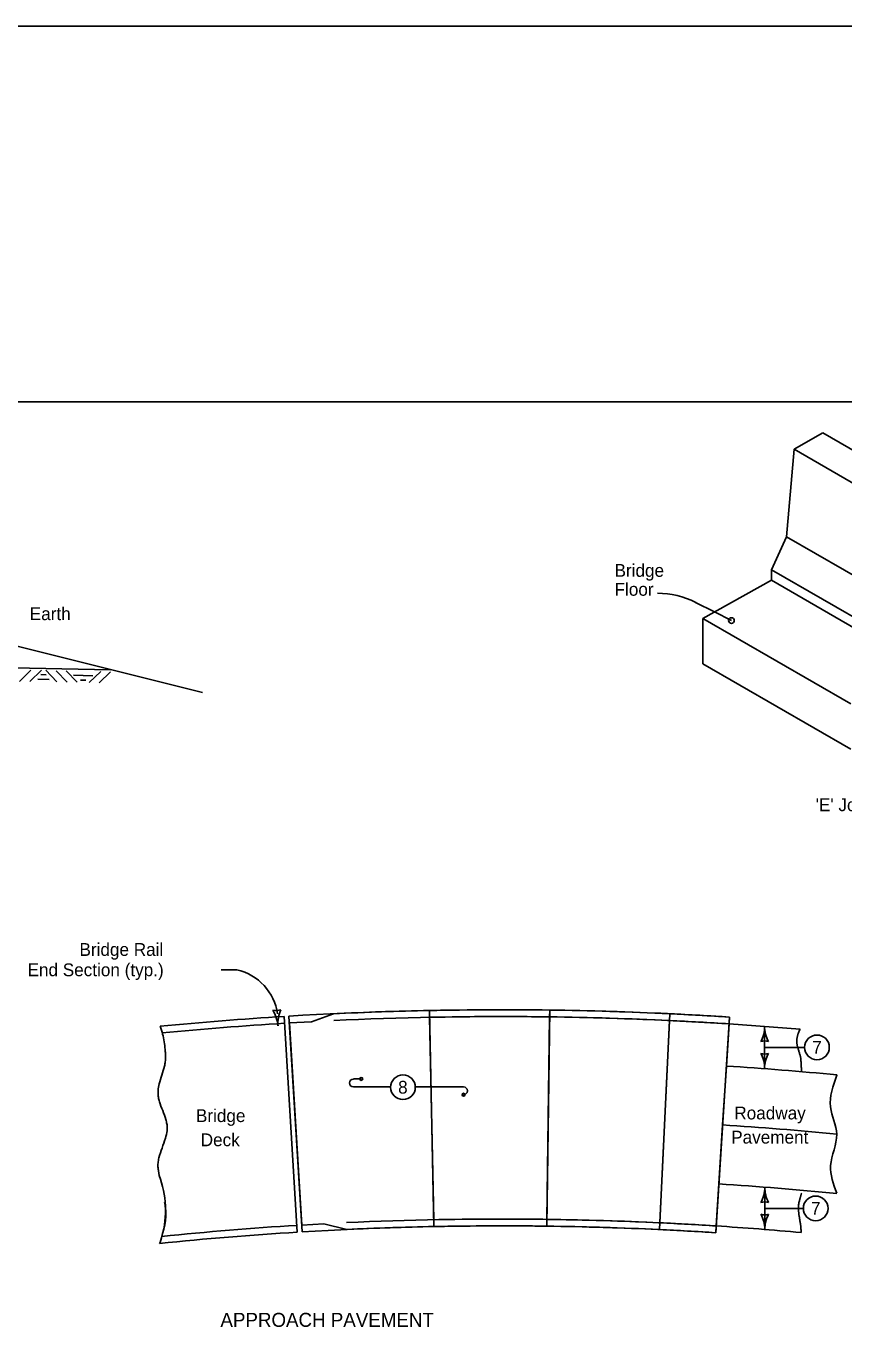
# Model space of a CAD drawing. Extents: x -2135039 to -2124495, y -2139046 to -2132546.
# Drawn here: x -2126601 to -2125580, y -2134174 to -2132546 of the extents above; entities that cross this region are included whole.
import ezdxf

# ---------------------------------------------------------------- set-up
doc = ezdxf.new("R2010")
doc.units = 0
for name, color, linetype in [('BridgeSuperStructureExisting', 7, 'Continuous'), ('Default', 7, 'Continuous'), ('dsnAlignmentStation', 7, 'Continuous'), ('dsnCellElements', 7, 'Continuous'), ('dsnStdLabel', 7, 'Continuous'), ('dsnStdLineWork', 7, 'Continuous'), ('TC_Barrier', 7, 'Continuous')]:
    doc.layers.add(name, color=color, linetype=linetype)

msp = doc.modelspace()

# ---------------------------------------------------------------- linework, layer by layer
at = {"layer": 'BridgeSuperStructureExisting'}
for p, q in [((-2125466.3, -2133291.3), (-2125651.3, -2133184.5)), ((-2125485.2, -2133332.6), (-2125670.2, -2133225.8)), ((-2125670.2, -2133225.8), (-2125670.2, -2133238.9)), ((-2125764.8, -2133266.6), (-2125741.4, -2133278.4)), ((-2125741.4, -2133278.4), (-2125720.1, -2133289.2)), ((-2126628.9, -2133317.2), (-2126380.7, -2133379.3)), ((-2126673.1, -2133347.1), (-2126495.3, -2133350.6)), ((-2126594.9, -2133351.3), (-2126609.3, -2133365.2)), ((-2126581.9, -2133351.3), (-2126596.3, -2133365.2)), ((-2126576.5, -2133351.4), (-2126562.6, -2133365.9)), ((-2126563.5, -2133351.9), (-2126549.6, -2133366.4)), ((-2126551, -2133352), (-2126537.2, -2133366.4)), ((-2126507.8, -2133352.8), (-2126522.2, -2133366.7)), ((-2126495.4, -2133353.3), (-2126509.8, -2133367.2)), ((-2126337.7, -2133725.6), (-2126357.2, -2133725.6)), ((-2126272.2, -2133792), (-2126244.6, -2133790.7)), ((-2126244.6, -2133790.7), (-2126272.2, -2133792)), ((-2126272.2, -2133792), (-2126256.6, -2134044.5)), ((-2126244.6, -2133790.7), (-2126217, -2133780.5)), ((-2126217, -2133780.5), (-2126244.6, -2133790.7)), ((-2126091.8, -2134046.4), (-2126097.3, -2133776.4)), ((-2126097.3, -2133776.4), (-2126097.1, -2133784.9)), ((-2126097.1, -2133784.9), (-2126097.3, -2133776.4)), ((-2126097.1, -2133784.9), (-2126091.9, -2134037.9)), ((-2126091.9, -2134037.9), (-2126097.1, -2133784.9)), ((-2125950.8, -2134045.9), (-2125947.1, -2133775.9)), ((-2125947.2, -2133784.4), (-2125950.7, -2134037.4)), ((-2125950.7, -2134037.4), (-2125947.2, -2133784.4)), ((-2125947.1, -2133775.9), (-2125947.2, -2133784.4)), ((-2125947.2, -2133784.4), (-2125947.1, -2133775.9)), ((-2125810, -2134050.2), (-2125797.2, -2133780.5)), ((-2125809.6, -2134041.7), (-2125797.6, -2133789)), ((-2125797.6, -2133789), (-2125809.6, -2134041.7)), ((-2125797.2, -2133780.5), (-2125797.6, -2133789)), ((-2125797.6, -2133789), (-2125797.2, -2133780.5)), ((-2125723, -2133793.1), (-2125722.4, -2133784.7)), ((-2125678.7, -2133849), (-2125678.7, -2133796.2)), ((-2125678.7, -2133822.5), (-2125649.2, -2133822.5)), ((-2125649.2, -2133822.5), (-2125628.6, -2133822.5)), ((-2126182.4, -2133862), (-2126192.2, -2133862)), ((-2126145.7, -2133871.9), (-2126192.2, -2133871.9)), ((-2126115, -2133871.9), (-2126054.7, -2133871.9)), ((-2126435, -2133982.6), (-2126436.1, -2133973.7)), ((-2125678.5, -2134050), (-2125678.5, -2133997.4)), ((-2125678.5, -2134023.7), (-2125649, -2134023.7)), ((-2125649, -2134023.7), (-2125630.2, -2134023.7)), ((-2126256.6, -2134044.5), (-2126229.1, -2134042.8)), ((-2126256.6, -2134044.5), (-2126229.1, -2134042.8)), ((-2126229.1, -2134042.8), (-2126200.5, -2134050)), ((-2126229.1, -2134042.8), (-2126200.5, -2134050)), ((-2126091.9, -2134037.9), (-2126091.8, -2134046.4)), ((-2126091.8, -2134046.4), (-2126091.9, -2134037.9)), ((-2125950.7, -2134037.4), (-2125950.8, -2134045.9)), ((-2125950.8, -2134045.9), (-2125950.7, -2134037.4)), ((-2125809.6, -2134041.7), (-2125810, -2134050.2)), ((-2125810, -2134050.2), (-2125809.6, -2134041.7)), ((-2125739.8, -2134054.1), (-2125739.2, -2134045.6))]:
    msp.add_line(p, q, dxfattribs=at)
for points in [[(-2125606, -2133054.7), (-2125240, -2133266), (-2125149.5, -2133318.2), (-2125104.3, -2133344.4), (-2125132.5, -2133360.7), (-2125185.3, -2133338.9), (-2125275.9, -2133286.7), (-2125456.9, -2133182.1), (-2125641.9, -2133075.3)], [(-2125641.9, -2133075.3), (-2125606, -2133054.7)], [(-2125670.2, -2133225.8), (-2125651.3, -2133184.5), (-2125641.9, -2133075.3)], [(-2125670.2, -2133238.9), (-2125756, -2133286.5)], [(-2125485.2, -2133345.7), (-2125670.2, -2133238.9)], [(-2125756, -2133286.5), (-2125571, -2133393.3)], [(-2125756, -2133343.1), (-2125756, -2133286.5)], [(-2125571, -2133449.9), (-2125756, -2133343.1)], [(-2126586.5, -2133362.6), (-2126572.3, -2133362.9)], [(-2126582.6, -2133356.8), (-2126576, -2133357)], [(-2126541.6, -2133357.6), (-2126517.5, -2133358.1)], [(-2126532.9, -2133363.6), (-2126526.4, -2133363.7)], [(-2125739.2, -2134045.6), (-2125735.8, -2133993), (-2125731.1, -2133919.4), (-2125726.4, -2133845.8), (-2125723, -2133793.1)]]:
    msp.add_lwpolyline(points, dxfattribs=at)
for centre in [(-2125613.3, -2133822.5), (-2126130.3, -2133872.3), (-2126130.3, -2133872.3), (-2125614.9, -2134023.7)]:
    msp.add_circle(centre, 15.4, dxfattribs=at)
for centre, radius, start, end in [((-2125812.5, -2133361.1), 105.9, 63.2177, 90), ((-2126352.8, -2133790.5), 66.7, 8.4828, 76.8823), ((-2126007.1, -2138203.4), 4427.9, 89.2234, 91.1665), ((-2126007.1, -2138203.4), 4427.9, 91.1665, 92.7162), ((-2126007.1, -2138203.4), 4419.4, 86.3134, 92.7162), ((-2126007.1, -2138203.4), 4419.4, 89.2234, 91.1665), ((-2126007.1, -2138203.4), 4419.4, 89.2234, 91.1665), ((-2126007.1, -2138203.4), 4419.4, 87.2821, 89.2234), ((-2126007.1, -2138203.4), 4419.4, 87.2821, 89.2234), ((-2126007.1, -2138203.4), 4427.9, 87.2821, 89.2234), ((-2126007.1, -2138203.4), 4419.4, 86.3134, 87.2821), ((-2126007.1, -2138203.4), 4419.4, 86.3134, 87.2821), ((-2126007.1, -2138203.4), 4427.9, 86.3134, 87.2821), ((-2126007.1, -2138203.4), 4419.4, 85.1616, 86.3134), ((-2125718.8, -2133796.2), 40.2, 331.9275, 360), ((-2125638.5, -2133796.2), 40.2, 180, 208.0725), ((-2125605, -2133816), 33.6, 151.08, 159.8686), ((-2125678.7, -2133829.9), 15.5, 72.2666, 107.7334), ((-2125678.7, -2133815.3), 15.5, 252.2666, 287.7333), ((-2125718.8, -2133849), 40.2, 360, 28.0725), ((-2125638.5, -2133849), 40.2, 151.9275, 180), ((-2126007.1, -2138203.4), 4366.6, 84.4974, 86.3134), ((-2125507.8, -2133892.3), 88, 156.2644, 156.5217), ((-2126192.2, -2133867), 4.92, 90, 270), ((-2126054.7, -2133876.8), 4.92, 270, 90), ((-2126545.3, -2134025.8), 118.5, 343.9162, 21.4054), ((-2126007.1, -2138203.4), 4219.1, 84.307, 86.3134), ((-2125718.7, -2133997.4), 40.2, 331.9275, 360), ((-2125638.3, -2133997.4), 40.2, 180, 208.0725), ((-2125678.5, -2134031.1), 15.5, 72.2666, 107.7334), ((-2125678.5, -2134016.3), 15.5, 252.2666, 287.7333), ((-2125718.7, -2134050), 40.2, 360, 28.0725), ((-2125638.3, -2134050), 40.2, 151.9275, 180), ((-2126007.1, -2138203.4), 4166.4, 86.3134, 92.666), ((-2126007.1, -2138203.4), 4157.9, 91.1665, 92.666), ((-2126007.1, -2138203.4), 4166.4, 89.2234, 91.1665), ((-2126007.1, -2138203.4), 4166.4, 89.2234, 91.1665), ((-2126007.1, -2138203.4), 4157.9, 89.2234, 91.1665), ((-2126007.1, -2138203.4), 4157.9, 87.2821, 89.2234), ((-2126007.1, -2138203.4), 4166.4, 87.2821, 89.2234), ((-2126007.1, -2138203.4), 4166.4, 87.2821, 89.2234), ((-2126007.1, -2138203.4), 4157.9, 86.3134, 87.2821), ((-2126007.1, -2138203.4), 4166.4, 86.3134, 87.2821), ((-2126007.1, -2138203.4), 4166.4, 86.3134, 87.2821), ((-2126007.1, -2138203.4), 4166.4, 84.8485, 86.3134)]:
    msp.add_arc(centre, radius, start, end, dxfattribs=at)
for points in [[(-2126433.6, -2133796.1), (-2126430.5, -2133805.8), (-2126428.5, -2133815.5), (-2126427.3, -2133825.2), (-2126427, -2133830.1), (-2126426.9, -2133834.9), (-2126427.2, -2133840.5), (-2126428.2, -2133846), (-2126431.4, -2133857.1), (-2126434.7, -2133868.2), (-2126436.1, -2133876.5), (-2126436.1, -2133877.9), (-2126436.2, -2133879.3), (-2126435.7, -2133884.9), (-2126434.4, -2133890.4), (-2126430.4, -2133901.5), (-2126426.5, -2133912.6), (-2126425.2, -2133918.1), (-2126424.8, -2133923.6), (-2126424.9, -2133925.2), (-2126425, -2133926.7), (-2126427, -2133936), (-2126431.2, -2133948.3), (-2126435.1, -2133960.7), (-2126436.2, -2133966.9), (-2126436.2, -2133973.2), (-2126435.9, -2133975.6)], [(-2125588.6, -2133857.2), (-2125596.3, -2133896.9), (-2125588.6, -2133931), (-2125596.3, -2133970.2), (-2125588.6, -2134004.7)], [(-2126428.1, -2134016.5), (-2126426.9, -2134022.7), (-2126433.7, -2134066.1)]]:
    msp.add_spline(points, degree=3, dxfattribs=at)
for points in [[(-2125636.5, -2133804.4), (-2125636.7, -2133804.9), (-2125636.9, -2133805.4), (-2125637, -2133805.9), (-2125637.2, -2133806.4), (-2125637.3, -2133806.9), (-2125637.4, -2133807.4), (-2125637.7, -2133808.4), (-2125637.9, -2133809.4), (-2125638.1, -2133810.4), (-2125638.3, -2133811.4), (-2125638.4, -2133812.4), (-2125638.4, -2133813.4), (-2125638.5, -2133813.9), (-2125638.5, -2133814.4), (-2125638.5, -2133814.9), (-2125638.5, -2133815.4), (-2125638.5, -2133815.9), (-2125638.4, -2133816.4), (-2125638.4, -2133817.3), (-2125638.3, -2133818.2), (-2125638.1, -2133819.2), (-2125638, -2133820.1), (-2125637.8, -2133821.1), (-2125637.5, -2133822), (-2125637, -2133823.9), (-2125636.4, -2133825.8), (-2125635.8, -2133827.6), (-2125635.3, -2133829.5), (-2125634.7, -2133831.4), (-2125634.2, -2133833.3), (-2125633.9, -2133834.2), (-2125633.7, -2133835.2), (-2125633.6, -2133836.2), (-2125633.4, -2133837.1), (-2125633.3, -2133838.1), (-2125633.3, -2133839.1), (-2125633.2, -2133840.6), (-2125633.1, -2133842.1), (-2125633, -2133843.6), (-2125633, -2133845.1), (-2125632.9, -2133846.6), (-2125632.8, -2133848.1), (-2125632.7, -2133849.6), (-2125632.7, -2133851.1), (-2125632.6, -2133852.6), (-2125632.6, -2133852.7), (-2125632.6, -2133852.8), (-2125632.6, -2133852.8)], [(-2125632.4, -2134004.7), (-2125632.8, -2134005.5), (-2125633.1, -2134006.4), (-2125633.3, -2134007.3), (-2125633.6, -2134008.2), (-2125633.9, -2134009.1), (-2125634.2, -2134009.9), (-2125634.7, -2134011.7), (-2125635.1, -2134013.4), (-2125635.5, -2134015.2), (-2125636, -2134017.8), (-2125636.4, -2134020.5), (-2125636.4, -2134023.2), (-2125636.4, -2134023.6), (-2125636.4, -2134024.1), (-2125636.4, -2134024.5), (-2125636.4, -2134024.9), (-2125636.4, -2134025.4), (-2125636.4, -2134025.8), (-2125636.3, -2134026.8), (-2125636.2, -2134027.8), (-2125636.1, -2134028.8), (-2125636, -2134029.8), (-2125635.9, -2134030.8), (-2125635.8, -2134031.8), (-2125635.4, -2134033.7), (-2125635.1, -2134035.7), (-2125634.8, -2134037.7), (-2125634.5, -2134039.7), (-2125634.2, -2134041.6), (-2125633.9, -2134043.6), (-2125633.7, -2134044.6), (-2125633.6, -2134045.6), (-2125633.5, -2134046.6), (-2125633.4, -2134047.6), (-2125633.3, -2134048.6), (-2125633.3, -2134049.6), (-2125633.2, -2134051), (-2125633.1, -2134052.4), (-2125633, -2134053.8)]]:
    msp.add_open_spline(points, degree=3, dxfattribs=at)
at = {"layer": 'Default'}
for p, q in [((-2126262.3, -2134053.3), (-2126278.8, -2133783.8)), ((-2126256.1, -2134053), (-2126272.7, -2133783.5)), ((-2125739.8, -2134054.1), (-2125722.4, -2133784.7))]:
    msp.add_line(p, q, dxfattribs=at)
for centre, radius, start, end in [((-2126007.1, -2138203.4), 4427.9, 86.3134, 93.4384), ((-2126007.1, -2138203.4), 4427.9, 93.5182, 95.527), ((-2126007.1, -2138203.4), 4419.4, 93.5182, 95.5028), ((-2126007.1, -2138203.4), 4292.9, 84.4047, 86.3134), ((-2126007.1, -2138203.4), 4166.4, 93.5182, 95.845), ((-2126007.1, -2138203.4), 4157.9, 86.3134, 93.4332), ((-2126007.1, -2138203.4), 4157.9, 93.5182, 95.8961), ((-2126564.7, -2134020.9), 138.6, 340.3486, 340.9778)]:
    msp.add_arc(centre, radius, start, end, dxfattribs=at)
at = {"layer": 'dsnAlignmentStation'}
msp.add_lwpolyline([(-2127734.4, -2133016), (-2124599.4, -2133016), (-2124599.4, -2135026), (-2127734.4, -2135026)], close=True, dxfattribs=at)
at = {"layer": 'dsnCellElements'}
for centre in [(-2126182.4, -2133862), (-2126054.7, -2133881.7)]:
    msp.add_circle(centre, 1.78, dxfattribs=at)
for centre, radius, start, end in [((-2126289.1, -2133760.2), 16.4, 256.6331, 292.0998), ((-2126244, -2133792.5), 42.5, 156.294, 184.3665), ((-2126328.8, -2133798.9), 42.5, 4.3665, 32.439)]:
    msp.add_arc(centre, radius, start, end, dxfattribs=at)
at = {"layer": 'dsnStdLineWork'}
msp.add_lwpolyline([(-2127838.9, -2135130.5), (-2124494.9, -2135130.5), (-2124494.9, -2132546.5), (-2127838.9, -2132546.5)], close=True, dxfattribs=at)
at = {"layer": 'TC_Barrier'}
msp.add_circle((-2125720.1, -2133289.2), 3.54, dxfattribs=at)

# ---------------------------------------------------------------- texts
at = {"layer": 'BridgeSuperStructureExisting'}
for s, height, p in [('Bridge', 16, (-2125866.1, -2133234.6)), ('Floor', 16, (-2125866.1, -2133258.2)), ("'E' Joint", 16, (-2125614.9, -2133527.4)), ('Bridge Rail', 16, (-2126534.3, -2133708.2)), ('End Section (typ.)', 16, (-2126599.2, -2133733.6)), ('APPROACH PAVEMENT', 17.5, (-2126358.3, -2134171.7))]:
    msp.add_text(s, height=height, dxfattribs=at).set_placement(p)
at = {"layer": 'dsnStdLabel'}
for s, p in [('Earth', (-2126596.4, -2133288.7)), ('7', (-2125619.2, -2133830.5)), ('8', (-2126136.4, -2133880.3)), ('Bridge', (-2126388.9, -2133915.8)), ('Roadway', (-2125716.5, -2133912.5)), ('Deck', (-2126382.9, -2133946)), ('Pavement', (-2125720.4, -2133942.7)), ('7', (-2125620.8, -2134031.7))]:
    msp.add_text(s, height=16, dxfattribs=at).set_placement(p)

doc.saveas('drawing.dxf')
